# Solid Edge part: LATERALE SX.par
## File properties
Subject: LATERALE SX
Author: f_grande
Template: Normal.par
Last saved by: f_grande
Revision: 18
Application: Solid Edge
Material: MDF
Stile della faccia: Marroncino
Coef. of Thermal Exp: 0.0
Thermal Conductivity: 0.0
Specific Heat: 0.0
Modulus of Elasticity: 0.0
Poisson's Ratio: 0.0
Yield Stress: 0.0
Ultimate Stress: 0.0
Elongation: 0.0
Tipo di contenuto documento: 0
Densità: 750,000 kg/m^3
Precisione: 0,990
Document Number: KR0116
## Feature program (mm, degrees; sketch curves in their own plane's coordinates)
sketch for "unnamed Protrusion 1" plane through (0, 0, 0) normal (0, -1, 0) x-axis (1, 0, 0)
  line (-31.1402, -42.2949) -> (158.8598, -42.2949)
  line (158.8598, 45.2051) -> (158.8598, -42.2949)
  line (158.8598, 45.2051) -> (41.5285, 477.7051)
  line (41.5285, 477.7051) -> (-45.4715, 477.7051)
  line (-106.4715, 384.7051) -> (-45.4715, 477.7051)
  line (-106.4715, 384.7051) -> (-106.4715, 314.7051)
  line (-106.4715, 314.7051) -> (-31.1402, 198.7051)
  line (-31.1402, -42.2949) -> (-31.1402, 198.7051)
  dimension (linear) = 31.1402
  dimension (linear) = 41.5285
  dimension (linear) = 106.4715
  dimension (linear) = 158.8598
  dimension (linear) = 31.1402
  dimension (linear) = 106.4715
extrude "unnamed Protrusion 1" add finite 19 along +normal
fillet "Rotondo_1" radius 5
sketch for "Foro_1" plane through (25.7098, -19, 217.2051) normal (0, -1, 0) x-axis (1, 0, 0)
  hole centre (-98.7813, 132.4938) bore radius 10
hole "Foro_1" diameter 20 through
sketch for "Foro_8" plane through (25.7098, 0, 217.2051) normal (0, 1, 0) x-axis (-1, 0, 0)
hole "Foro_8" diameter 9 through
sketch for "unnamed Hole 1" plane through (25.7098, 0, 217.2051) normal (0, 1, 0) x-axis (-1, 0, 0)
hole "unnamed Hole 1" through
sketch for "unnamed Hole 2" plane through (25.7098, 0, 217.2051) normal (0, 1, 0) x-axis (-1, 0, 0)
  hole centre (-15.6, -203.9) bore radius 4.5
hole "unnamed Hole 2" through
sketch for "unnamed Hole 3" plane through (25.7098, 0, 217.2051) normal (0, 1, 0) x-axis (-1, 0, 0)
hole "unnamed Hole 3" through
pattern "unnamed Pattern 1" of "Foro_8", "unnamed Hole 1", "unnamed Hole 2", "unnamed Hole 3"
sketch for "Foro_12" plane through (25.7098, 0, 217.2051) normal (0, 1, 0) x-axis (-1, 0, 0)
hole "Foro_12" diameter 9 through
sketch for "unnamed Hole 4" plane through (25.7098, 0, 217.2051) normal (0, 1, 0) x-axis (-1, 0, 0)
hole "unnamed Hole 4" through
pattern "unnamed Pattern 2" of "Foro_12", "unnamed Hole 4"
fillet "Rotondo_4" radius 50
sketch for "Foro_14" plane through (26.1942, -19, 217.7051) normal (0, -1, 0) x-axis (1, 0, 0)
hole "Foro_14" diameter 5 through
sketch for "unnamed Hole 5" plane through (26.1942, -19, 217.7051) normal (0, -1, 0) x-axis (1, 0, 0)
  hole centre (-75.6956, 155.5638) bore radius 2.5
hole "unnamed Hole 5" through
sketch for "unnamed Hole 6" plane through (26.1942, -19, 217.7051) normal (0, -1, 0) x-axis (1, 0, 0)
  hole centre (-75.6956, 108.4238) bore radius 2.5
hole "unnamed Hole 6" through
sketch for "unnamed Hole 7" plane through (26.1942, -19, 217.7051) normal (0, -1, 0) x-axis (1, 0, 0)
hole "unnamed Hole 7" through
pattern "unnamed Pattern 3" of "Foro_14", "unnamed Hole 5", "unnamed Hole 6", "unnamed Hole 7"
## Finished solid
Body 1: solid body, 26 faces, 61 edges, 26 vertices.
  Faces by surface: cylinder 16, plane 10
  Edges by curve: circle 32, line 29
Bounding box of the edges (mm): 265.331 x 19.000 x 520.000, from (-106.4715, -19, -42.2949) to (158.8598, 0, 477.7051).
Cylindrical faces by radius (mm): R2.5 x4, R4.5 x6, R5 x4, R10 x1, R50 x1
Planar faces by outward normal: +x 1, +y 1, +z 1, -x 2, -y 1, -z 1, oblique 3
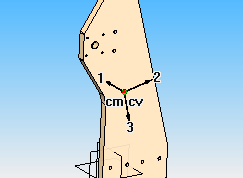
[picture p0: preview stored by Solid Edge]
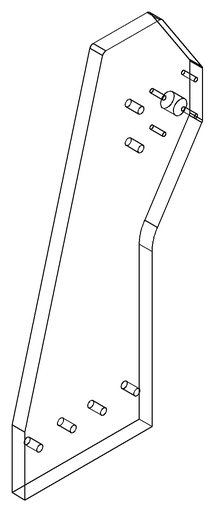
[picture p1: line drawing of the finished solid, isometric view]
